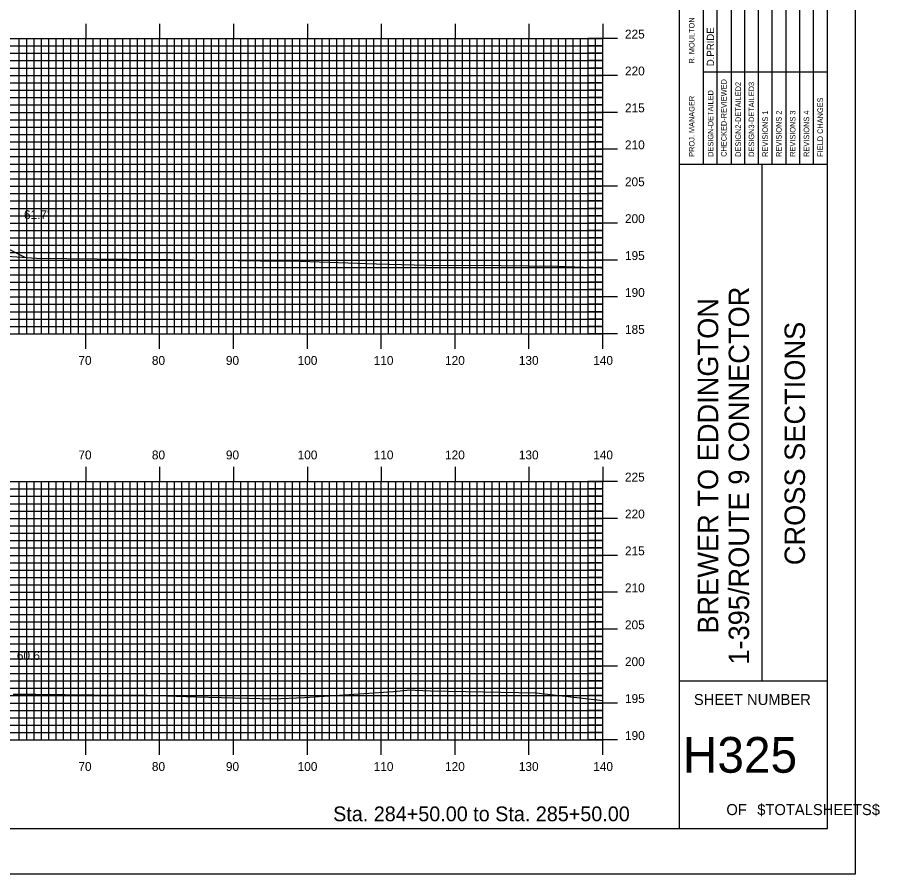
# Model space of a CAD drawing. Extents: x 1812161 to 1812504, y 442591 to 442811.
# Drawn here: x 1812387.2 to 1812503.9, y 442590.5 to 442706.6 of the extents above; entities that cross this region are included whole.
import ezdxf

# ---------------------------------------------------------------- set-up
doc = ezdxf.new("R2010")
doc.units = 0
for name, color, linetype in [('BORDER', 7, 'Continuous'), ('D_Roadway_Centerline', 7, 'Continuous'), ('D_Roadway_SlopeLines', 7, 'Continuous'), ('D_Text_Standard', 7, 'Continuous'), ('H_V ANNOTATION', 7, 'Continuous'), ('MAJOR', 7, 'Continuous'), ('MINOR', 7, 'Continuous'), ('PLOT BOUNDARY', 7, 'Continuous'), ('S_Roadway_Centerline', 7, 'Continuous')]:
    doc.layers.add(name, color=color, linetype=linetype)

msp = doc.modelspace()

# ---------------------------------------------------------------- linework, layer by layer
at = {"layer": 'BORDER'}
for p, q in [((1812476.83, 442596.67), (1812476.83, 442806.67)), ((1812476.83, 442686.67), (1812496.83, 442686.67)), ((1812488.01, 442616.67), (1812488.01, 442686.67)), ((1812476.83, 442616.67), (1812496.83, 442616.67))]:
    msp.add_line(p, q, dxfattribs=at)
msp.add_lwpolyline([(1812176.83, 442596.67), (1812496.83, 442596.67), (1812496.83, 442806.67), (1812176.83, 442806.67)], close=True, dxfattribs=at)
for points in [[(1812481.92, 442686.68), (1812481.92, 442721.67)], [(1812483.79, 442721.67), (1812483.79, 442686.68)], [(1812485.65, 442686.68), (1812485.65, 442721.67)], [(1812487.51, 442686.68), (1812487.51, 442721.67)], [(1812489.38, 442686.68), (1812489.38, 442721.67)], [(1812491.24, 442686.68), (1812491.24, 442721.67)], [(1812493.1, 442686.68), (1812493.1, 442721.67)], [(1812494.97, 442686.68), (1812494.97, 442721.67)], [(1812480.06, 442686.68), (1812480.06, 442720.26)], [(1812480.06, 442699.17), (1812496.83, 442699.17)]]:
    msp.add_lwpolyline(points, dxfattribs=at)
at = {"layer": 'D_Roadway_Centerline'}
msp.add_lwpolyline([(1812264.46, 442675.39), (1812298.22, 442692.27), (1812303.43, 442694.88), (1812306.43, 442694.94), (1812314.43, 442695.1), (1812326.43, 442694.52), (1812338.43, 442693.94), (1812346.43, 442693.56), (1812349.43, 442693.42), (1812354.96, 442690.65), (1812388.17, 442674.04)], dxfattribs=at)
at = {"layer": 'D_Roadway_SlopeLines'}
msp.add_lwpolyline([(1812349.43, 442693.42), (1812388.17, 442674.04)], dxfattribs=at)
at = {"layer": 'MAJOR'}
for p, q in [((1812396.43, 442705.67), (1812396.43, 442703.67)), ((1812406.43, 442705.67), (1812406.43, 442703.67)), ((1812416.43, 442705.67), (1812416.43, 442703.67)), ((1812426.43, 442705.67), (1812426.43, 442703.67)), ((1812436.43, 442705.67), (1812436.43, 442703.67)), ((1812446.43, 442705.67), (1812446.43, 442703.67)), ((1812456.43, 442705.67), (1812456.43, 442703.67)), ((1812466.43, 442705.67), (1812466.43, 442703.67)), ((1812186.43, 442703.67), (1812466.43, 442703.67)), ((1812186.43, 442703.67), (1812466.43, 442703.67)), ((1812396.43, 442663.67), (1812396.43, 442703.67)), ((1812406.43, 442663.67), (1812406.43, 442703.67)), ((1812416.43, 442663.67), (1812416.43, 442703.67)), ((1812426.43, 442663.67), (1812426.43, 442703.67)), ((1812436.43, 442663.67), (1812436.43, 442703.67)), ((1812446.43, 442663.67), (1812446.43, 442703.67)), ((1812456.43, 442663.67), (1812456.43, 442703.67)), ((1812468.43, 442703.67), (1812464.42, 442703.67)), ((1812466.43, 442663.67), (1812466.43, 442703.67)), ((1812466.43, 442663.67), (1812466.43, 442703.67)), ((1812186.43, 442698.67), (1812466.43, 442698.67)), ((1812468.43, 442698.67), (1812464.42, 442698.67)), ((1812186.43, 442693.67), (1812466.43, 442693.67)), ((1812468.43, 442693.67), (1812464.42, 442693.67)), ((1812186.43, 442688.67), (1812466.43, 442688.67)), ((1812468.43, 442688.67), (1812464.42, 442688.67)), ((1812186.43, 442683.67), (1812466.43, 442683.67)), ((1812468.43, 442683.67), (1812464.42, 442683.67)), ((1812186.43, 442678.67), (1812466.43, 442678.67)), ((1812468.43, 442678.67), (1812464.42, 442678.67)), ((1812186.43, 442673.67), (1812466.43, 442673.67)), ((1812468.43, 442673.67), (1812464.42, 442673.67)), ((1812186.43, 442668.67), (1812466.43, 442668.67)), ((1812468.43, 442668.67), (1812464.42, 442668.67)), ((1812186.43, 442663.67), (1812466.43, 442663.67)), ((1812186.43, 442663.67), (1812466.43, 442663.67)), ((1812396.43, 442661.66), (1812396.43, 442663.67)), ((1812406.43, 442661.66), (1812406.43, 442663.67)), ((1812416.43, 442661.66), (1812416.43, 442663.67)), ((1812426.43, 442661.66), (1812426.43, 442663.67)), ((1812436.43, 442661.66), (1812436.43, 442663.67)), ((1812446.43, 442661.66), (1812446.43, 442663.67)), ((1812456.43, 442661.66), (1812456.43, 442663.67)), ((1812468.43, 442663.67), (1812464.42, 442663.67)), ((1812466.43, 442661.66), (1812466.43, 442663.67)), ((1812396.43, 442645.67), (1812396.43, 442643.67)), ((1812406.43, 442645.67), (1812406.43, 442643.67)), ((1812416.43, 442645.67), (1812416.43, 442643.67)), ((1812426.43, 442645.67), (1812426.43, 442643.67)), ((1812436.43, 442645.67), (1812436.43, 442643.67)), ((1812446.43, 442645.67), (1812446.43, 442643.67)), ((1812456.43, 442645.67), (1812456.43, 442643.67)), ((1812466.43, 442645.67), (1812466.43, 442643.67)), ((1812186.43, 442643.67), (1812466.43, 442643.67)), ((1812186.43, 442643.67), (1812466.43, 442643.67)), ((1812396.43, 442608.67), (1812396.43, 442643.67)), ((1812406.43, 442608.67), (1812406.43, 442643.67)), ((1812416.43, 442608.67), (1812416.43, 442643.67)), ((1812426.43, 442608.67), (1812426.43, 442643.67)), ((1812436.43, 442608.67), (1812436.43, 442643.67)), ((1812446.43, 442608.67), (1812446.43, 442643.67)), ((1812456.43, 442608.67), (1812456.43, 442643.67)), ((1812468.43, 442643.67), (1812464.42, 442643.67)), ((1812466.43, 442608.67), (1812466.43, 442643.67)), ((1812466.43, 442608.67), (1812466.43, 442643.67)), ((1812186.43, 442638.67), (1812466.43, 442638.67)), ((1812468.43, 442638.67), (1812464.42, 442638.67)), ((1812186.43, 442633.67), (1812466.43, 442633.67)), ((1812468.43, 442633.67), (1812464.42, 442633.67)), ((1812186.43, 442628.67), (1812466.43, 442628.67)), ((1812468.43, 442628.67), (1812464.42, 442628.67)), ((1812186.43, 442623.67), (1812466.43, 442623.67)), ((1812468.43, 442623.67), (1812464.42, 442623.67)), ((1812186.43, 442618.67), (1812466.43, 442618.67)), ((1812468.43, 442618.67), (1812464.42, 442618.67)), ((1812186.43, 442613.67), (1812466.43, 442613.67)), ((1812468.43, 442613.67), (1812464.42, 442613.67)), ((1812186.43, 442608.67), (1812466.43, 442608.67)), ((1812186.43, 442608.67), (1812466.43, 442608.67)), ((1812396.43, 442606.66), (1812396.43, 442608.67)), ((1812406.43, 442606.66), (1812406.43, 442608.67)), ((1812416.43, 442606.66), (1812416.43, 442608.67)), ((1812426.43, 442606.66), (1812426.43, 442608.67)), ((1812436.43, 442606.66), (1812436.43, 442608.67)), ((1812446.43, 442606.66), (1812446.43, 442608.67)), ((1812456.43, 442606.66), (1812456.43, 442608.67)), ((1812468.43, 442608.67), (1812464.42, 442608.67)), ((1812466.43, 442606.66), (1812466.43, 442608.67))]:
    msp.add_line(p, q, dxfattribs=at)
at = {"layer": 'MINOR'}
for p, q in [((1812387.43, 442663.67), (1812387.43, 442703.67)), ((1812388.43, 442663.67), (1812388.43, 442703.67)), ((1812389.43, 442663.67), (1812389.43, 442703.67)), ((1812390.43, 442663.67), (1812390.43, 442703.67)), ((1812391.43, 442663.67), (1812391.43, 442703.67)), ((1812392.43, 442663.67), (1812392.43, 442703.67)), ((1812393.43, 442663.67), (1812393.43, 442703.67)), ((1812394.43, 442663.67), (1812394.43, 442703.67)), ((1812395.43, 442663.67), (1812395.43, 442703.67)), ((1812397.43, 442663.67), (1812397.43, 442703.67)), ((1812398.43, 442663.67), (1812398.43, 442703.67)), ((1812399.43, 442663.67), (1812399.43, 442703.67)), ((1812400.43, 442663.67), (1812400.43, 442703.67)), ((1812401.43, 442663.67), (1812401.43, 442703.67)), ((1812402.43, 442663.67), (1812402.43, 442703.67)), ((1812403.43, 442663.67), (1812403.43, 442703.67)), ((1812404.43, 442663.67), (1812404.43, 442703.67)), ((1812405.43, 442663.67), (1812405.43, 442703.67)), ((1812407.43, 442663.67), (1812407.43, 442703.67)), ((1812408.43, 442663.67), (1812408.43, 442703.67)), ((1812409.43, 442663.67), (1812409.43, 442703.67)), ((1812410.43, 442663.67), (1812410.43, 442703.67)), ((1812411.43, 442663.67), (1812411.43, 442703.67)), ((1812412.43, 442663.67), (1812412.43, 442703.67)), ((1812413.43, 442663.67), (1812413.43, 442703.67)), ((1812414.43, 442663.67), (1812414.43, 442703.67)), ((1812415.43, 442663.67), (1812415.43, 442703.67)), ((1812417.43, 442663.67), (1812417.43, 442703.67)), ((1812418.43, 442663.67), (1812418.43, 442703.67)), ((1812419.43, 442663.67), (1812419.43, 442703.67)), ((1812420.43, 442663.67), (1812420.43, 442703.67)), ((1812421.43, 442663.67), (1812421.43, 442703.67)), ((1812422.43, 442663.67), (1812422.43, 442703.67)), ((1812423.43, 442663.67), (1812423.43, 442703.67)), ((1812424.43, 442663.67), (1812424.43, 442703.67)), ((1812425.43, 442663.67), (1812425.43, 442703.67)), ((1812427.43, 442663.67), (1812427.43, 442703.67)), ((1812428.43, 442663.67), (1812428.43, 442703.67)), ((1812429.43, 442663.67), (1812429.43, 442703.67)), ((1812430.43, 442663.67), (1812430.43, 442703.67)), ((1812431.43, 442663.67), (1812431.43, 442703.67)), ((1812432.43, 442663.67), (1812432.43, 442703.67)), ((1812433.43, 442663.67), (1812433.43, 442703.67)), ((1812434.43, 442663.67), (1812434.43, 442703.67)), ((1812435.43, 442663.67), (1812435.43, 442703.67)), ((1812437.43, 442663.67), (1812437.43, 442703.67)), ((1812438.43, 442663.67), (1812438.43, 442703.67)), ((1812439.43, 442663.67), (1812439.43, 442703.67)), ((1812440.43, 442663.67), (1812440.43, 442703.67)), ((1812441.43, 442663.67), (1812441.43, 442703.67)), ((1812442.43, 442663.67), (1812442.43, 442703.67)), ((1812443.43, 442663.67), (1812443.43, 442703.67)), ((1812444.43, 442663.67), (1812444.43, 442703.67)), ((1812445.43, 442663.67), (1812445.43, 442703.67)), ((1812447.43, 442663.67), (1812447.43, 442703.67)), ((1812448.43, 442663.67), (1812448.43, 442703.67)), ((1812449.43, 442663.67), (1812449.43, 442703.67)), ((1812450.43, 442663.67), (1812450.43, 442703.67)), ((1812451.43, 442663.67), (1812451.43, 442703.67)), ((1812452.43, 442663.67), (1812452.43, 442703.67)), ((1812453.43, 442663.67), (1812453.43, 442703.67)), ((1812454.43, 442663.67), (1812454.43, 442703.67)), ((1812455.43, 442663.67), (1812455.43, 442703.67)), ((1812457.43, 442663.67), (1812457.43, 442703.67)), ((1812458.43, 442663.67), (1812458.43, 442703.67)), ((1812459.43, 442663.67), (1812459.43, 442703.67)), ((1812460.43, 442663.67), (1812460.43, 442703.67)), ((1812461.43, 442663.67), (1812461.43, 442703.67)), ((1812462.43, 442663.67), (1812462.43, 442703.67)), ((1812463.43, 442663.67), (1812463.43, 442703.67)), ((1812464.43, 442663.67), (1812464.43, 442703.67)), ((1812465.43, 442663.67), (1812465.43, 442703.67)), ((1812186.43, 442702.67), (1812466.43, 442702.67)), ((1812186.43, 442701.67), (1812466.43, 442701.67)), ((1812466.43, 442702.67), (1812464.42, 442702.67)), ((1812466.43, 442701.67), (1812464.42, 442701.67)), ((1812186.43, 442700.67), (1812466.43, 442700.67)), ((1812466.43, 442700.67), (1812464.42, 442700.67)), ((1812186.43, 442699.67), (1812466.43, 442699.67)), ((1812466.43, 442699.67), (1812464.42, 442699.67)), ((1812186.43, 442697.67), (1812466.43, 442697.67)), ((1812466.43, 442697.67), (1812464.42, 442697.67)), ((1812186.43, 442696.67), (1812466.43, 442696.67)), ((1812466.43, 442696.67), (1812464.42, 442696.67)), ((1812186.43, 442695.67), (1812466.43, 442695.67)), ((1812186.43, 442694.67), (1812466.43, 442694.67)), ((1812466.43, 442695.67), (1812464.42, 442695.67)), ((1812466.43, 442694.67), (1812464.42, 442694.67)), ((1812186.43, 442692.67), (1812466.43, 442692.67)), ((1812466.43, 442692.67), (1812464.42, 442692.67)), ((1812186.43, 442691.67), (1812466.43, 442691.67)), ((1812466.43, 442691.67), (1812464.42, 442691.67)), ((1812186.43, 442690.67), (1812466.43, 442690.67)), ((1812466.43, 442690.67), (1812464.42, 442690.67)), ((1812186.43, 442689.67), (1812466.43, 442689.67)), ((1812466.43, 442689.67), (1812464.42, 442689.67)), ((1812186.43, 442687.67), (1812466.43, 442687.67)), ((1812466.43, 442687.67), (1812464.42, 442687.67)), ((1812186.43, 442686.67), (1812466.43, 442686.67)), ((1812466.43, 442686.67), (1812464.42, 442686.67)), ((1812186.43, 442685.67), (1812466.43, 442685.67)), ((1812466.43, 442685.67), (1812464.42, 442685.67)), ((1812186.43, 442684.67), (1812466.43, 442684.67)), ((1812466.43, 442684.67), (1812464.42, 442684.67)), ((1812186.43, 442682.67), (1812466.43, 442682.67)), ((1812186.43, 442681.67), (1812466.43, 442681.67)), ((1812466.43, 442682.67), (1812464.42, 442682.67)), ((1812466.43, 442681.67), (1812464.42, 442681.67)), ((1812186.43, 442680.67), (1812466.43, 442680.67)), ((1812466.43, 442680.67), (1812464.42, 442680.67)), ((1812186.43, 442679.67), (1812466.43, 442679.67)), ((1812466.43, 442679.67), (1812464.42, 442679.67)), ((1812186.43, 442677.67), (1812466.43, 442677.67)), ((1812466.43, 442677.67), (1812464.42, 442677.67)), ((1812186.43, 442676.67), (1812466.43, 442676.67)), ((1812466.43, 442676.67), (1812464.42, 442676.67)), ((1812186.43, 442675.67), (1812466.43, 442675.67)), ((1812186.43, 442674.67), (1812466.43, 442674.67)), ((1812466.43, 442675.67), (1812464.42, 442675.67)), ((1812466.43, 442674.67), (1812464.42, 442674.67)), ((1812186.43, 442672.67), (1812466.43, 442672.67)), ((1812466.43, 442672.67), (1812464.42, 442672.67)), ((1812186.43, 442671.67), (1812466.43, 442671.67)), ((1812466.43, 442671.67), (1812464.42, 442671.67)), ((1812186.43, 442670.67), (1812466.43, 442670.67)), ((1812466.43, 442670.67), (1812464.42, 442670.67)), ((1812186.43, 442669.67), (1812466.43, 442669.67)), ((1812466.43, 442669.67), (1812464.42, 442669.67)), ((1812186.43, 442667.67), (1812466.43, 442667.67)), ((1812466.43, 442667.67), (1812464.42, 442667.67)), ((1812186.43, 442666.67), (1812466.43, 442666.67)), ((1812466.43, 442666.67), (1812464.42, 442666.67)), ((1812186.43, 442665.67), (1812466.43, 442665.67)), ((1812466.43, 442665.67), (1812464.42, 442665.67)), ((1812186.43, 442664.67), (1812466.43, 442664.67)), ((1812466.43, 442664.67), (1812464.42, 442664.67)), ((1812387.43, 442608.67), (1812387.43, 442643.67)), ((1812388.43, 442608.67), (1812388.43, 442643.67)), ((1812389.43, 442608.67), (1812389.43, 442643.67)), ((1812390.43, 442608.67), (1812390.43, 442643.67)), ((1812391.43, 442608.67), (1812391.43, 442643.67)), ((1812392.43, 442608.67), (1812392.43, 442643.67)), ((1812393.43, 442608.67), (1812393.43, 442643.67)), ((1812394.43, 442608.67), (1812394.43, 442643.67)), ((1812395.43, 442608.67), (1812395.43, 442643.67)), ((1812397.43, 442608.67), (1812397.43, 442643.67)), ((1812398.43, 442608.67), (1812398.43, 442643.67)), ((1812399.43, 442608.67), (1812399.43, 442643.67)), ((1812400.43, 442608.67), (1812400.43, 442643.67)), ((1812401.43, 442608.67), (1812401.43, 442643.67)), ((1812402.43, 442608.67), (1812402.43, 442643.67)), ((1812403.43, 442608.67), (1812403.43, 442643.67)), ((1812404.43, 442608.67), (1812404.43, 442643.67)), ((1812405.43, 442608.67), (1812405.43, 442643.67)), ((1812407.43, 442608.67), (1812407.43, 442643.67)), ((1812408.43, 442608.67), (1812408.43, 442643.67)), ((1812409.43, 442608.67), (1812409.43, 442643.67)), ((1812410.43, 442608.67), (1812410.43, 442643.67)), ((1812411.43, 442608.67), (1812411.43, 442643.67)), ((1812412.43, 442608.67), (1812412.43, 442643.67)), ((1812413.43, 442608.67), (1812413.43, 442643.67)), ((1812414.43, 442608.67), (1812414.43, 442643.67)), ((1812415.43, 442608.67), (1812415.43, 442643.67)), ((1812417.43, 442608.67), (1812417.43, 442643.67)), ((1812418.43, 442608.67), (1812418.43, 442643.67)), ((1812419.43, 442608.67), (1812419.43, 442643.67)), ((1812420.43, 442608.67), (1812420.43, 442643.67)), ((1812421.43, 442608.67), (1812421.43, 442643.67)), ((1812422.43, 442608.67), (1812422.43, 442643.67)), ((1812423.43, 442608.67), (1812423.43, 442643.67)), ((1812424.43, 442608.67), (1812424.43, 442643.67)), ((1812425.43, 442608.67), (1812425.43, 442643.67)), ((1812427.43, 442608.67), (1812427.43, 442643.67)), ((1812428.43, 442608.67), (1812428.43, 442643.67)), ((1812429.43, 442608.67), (1812429.43, 442643.67)), ((1812430.43, 442608.67), (1812430.43, 442643.67)), ((1812431.43, 442608.67), (1812431.43, 442643.67)), ((1812432.43, 442608.67), (1812432.43, 442643.67)), ((1812433.43, 442608.67), (1812433.43, 442643.67)), ((1812434.43, 442608.67), (1812434.43, 442643.67)), ((1812435.43, 442608.67), (1812435.43, 442643.67)), ((1812437.43, 442608.67), (1812437.43, 442643.67)), ((1812438.43, 442608.67), (1812438.43, 442643.67)), ((1812439.43, 442608.67), (1812439.43, 442643.67)), ((1812440.43, 442608.67), (1812440.43, 442643.67)), ((1812441.43, 442608.67), (1812441.43, 442643.67)), ((1812442.43, 442608.67), (1812442.43, 442643.67)), ((1812443.43, 442608.67), (1812443.43, 442643.67)), ((1812444.43, 442608.67), (1812444.43, 442643.67)), ((1812445.43, 442608.67), (1812445.43, 442643.67)), ((1812447.43, 442608.67), (1812447.43, 442643.67)), ((1812448.43, 442608.67), (1812448.43, 442643.67)), ((1812449.43, 442608.67), (1812449.43, 442643.67)), ((1812450.43, 442608.67), (1812450.43, 442643.67)), ((1812451.43, 442608.67), (1812451.43, 442643.67)), ((1812452.43, 442608.67), (1812452.43, 442643.67)), ((1812453.43, 442608.67), (1812453.43, 442643.67)), ((1812454.43, 442608.67), (1812454.43, 442643.67)), ((1812455.43, 442608.67), (1812455.43, 442643.67)), ((1812457.43, 442608.67), (1812457.43, 442643.67)), ((1812458.43, 442608.67), (1812458.43, 442643.67)), ((1812459.43, 442608.67), (1812459.43, 442643.67)), ((1812460.43, 442608.67), (1812460.43, 442643.67)), ((1812461.43, 442608.67), (1812461.43, 442643.67)), ((1812462.43, 442608.67), (1812462.43, 442643.67)), ((1812463.43, 442608.67), (1812463.43, 442643.67)), ((1812464.43, 442608.67), (1812464.43, 442643.67)), ((1812465.43, 442608.67), (1812465.43, 442643.67)), ((1812186.43, 442642.67), (1812466.43, 442642.67)), ((1812466.43, 442642.67), (1812464.42, 442642.67)), ((1812186.43, 442641.67), (1812466.43, 442641.67)), ((1812466.43, 442641.67), (1812464.42, 442641.67)), ((1812186.43, 442640.67), (1812466.43, 442640.67)), ((1812186.43, 442639.67), (1812466.43, 442639.67)), ((1812466.43, 442640.67), (1812464.42, 442640.67)), ((1812466.43, 442639.67), (1812464.42, 442639.67)), ((1812186.43, 442637.67), (1812466.43, 442637.67)), ((1812466.43, 442637.67), (1812464.42, 442637.67)), ((1812186.43, 442636.67), (1812466.43, 442636.67)), ((1812466.43, 442636.67), (1812464.42, 442636.67)), ((1812186.43, 442635.67), (1812466.43, 442635.67)), ((1812466.43, 442635.67), (1812464.42, 442635.67)), ((1812186.43, 442634.67), (1812466.43, 442634.67)), ((1812466.43, 442634.67), (1812464.42, 442634.67)), ((1812186.43, 442632.67), (1812466.43, 442632.67)), ((1812466.43, 442632.67), (1812464.42, 442632.67)), ((1812186.43, 442631.67), (1812466.43, 442631.67)), ((1812466.43, 442631.67), (1812464.42, 442631.67)), ((1812186.43, 442630.67), (1812466.43, 442630.67)), ((1812466.43, 442630.67), (1812464.42, 442630.67)), ((1812186.43, 442629.67), (1812466.43, 442629.67)), ((1812466.43, 442629.67), (1812464.42, 442629.67)), ((1812186.43, 442627.67), (1812466.43, 442627.67)), ((1812466.43, 442627.67), (1812464.42, 442627.67)), ((1812186.43, 442626.67), (1812466.43, 442626.67)), ((1812186.43, 442625.67), (1812466.43, 442625.67)), ((1812466.43, 442626.67), (1812464.42, 442626.67)), ((1812466.43, 442625.67), (1812464.42, 442625.67)), ((1812186.43, 442624.67), (1812466.43, 442624.67)), ((1812466.43, 442624.67), (1812464.42, 442624.67)), ((1812186.43, 442622.67), (1812466.43, 442622.67)), ((1812466.43, 442622.67), (1812464.42, 442622.67)), ((1812186.43, 442621.67), (1812466.43, 442621.67)), ((1812466.43, 442621.67), (1812464.42, 442621.67)), ((1812186.43, 442620.67), (1812466.43, 442620.67)), ((1812466.43, 442620.67), (1812464.42, 442620.67)), ((1812186.43, 442619.67), (1812466.43, 442619.67)), ((1812466.43, 442619.67), (1812464.42, 442619.67)), ((1812186.43, 442617.67), (1812466.43, 442617.67)), ((1812466.43, 442617.67), (1812464.42, 442617.67)), ((1812186.43, 442616.67), (1812466.43, 442616.67)), ((1812466.43, 442616.67), (1812464.42, 442616.67)), ((1812186.43, 442615.67), (1812466.43, 442615.67)), ((1812466.43, 442615.67), (1812464.42, 442615.67)), ((1812186.43, 442614.67), (1812466.43, 442614.67)), ((1812466.43, 442614.67), (1812464.42, 442614.67)), ((1812186.43, 442612.67), (1812466.43, 442612.67)), ((1812186.43, 442611.67), (1812466.43, 442611.67)), ((1812466.43, 442612.67), (1812464.42, 442612.67)), ((1812466.43, 442611.67), (1812464.42, 442611.67)), ((1812186.43, 442610.67), (1812466.43, 442610.67)), ((1812466.43, 442610.67), (1812464.42, 442610.67)), ((1812186.43, 442609.67), (1812466.43, 442609.67)), ((1812466.43, 442609.67), (1812464.42, 442609.67))]:
    msp.add_line(p, q, dxfattribs=at)
at = {"layer": 'PLOT BOUNDARY'}
msp.add_lwpolyline([(1812160.64, 442590.55), (1812500.64, 442590.55), (1812500.64, 442810.55), (1812160.64, 442810.55)], close=True, dxfattribs=at)
at = {"layer": 'S_Roadway_Centerline'}
for points in [[(1812382.38, 442674.43), (1812389.75, 442673.94), (1812406.13, 442673.75), (1812407.98, 442673.74), (1812420.04, 442673.57), (1812425.45, 442673.53), (1812435.8, 442673.14), (1812442.62, 442672.96), (1812452.64, 442672.93), (1812460.31, 442672.85), (1812466.16, 442672.62), (1812466.43, 442672.61)], [(1812386.61, 442614.87), (1812389.66, 442614.89), (1812397.53, 442614.8), (1812403.33, 442614.75), (1812404.74, 442614.72), (1812411.31, 442614.52), (1812421.74, 442614.22), (1812426.05, 442614.4), (1812438.08, 442615.25), (1812440.35, 442615.44), (1812441.01, 442615.41), (1812443.08, 442615.31), (1812457.43, 442615.04), (1812466.43, 442614.02)]]:
    msp.add_lwpolyline(points, dxfattribs=at)

# ---------------------------------------------------------------- texts
at = {"layer": 'BORDER'}
for s, height, p in [('R. MOULTON', 0.745, (1812478.84, 442700.28)), ('D.PRIDE', 0.969, (1812481.48, 442699.92)), ('CHECKED-REVIEWED', 0.7455, (1812483.19, 442687.65)), ('DESIGN2-DETAILED2', 0.7455, (1812485.13, 442687.65)), ('DESIGN3-DETAILED3', 0.7455, (1812486.92, 442687.65)), ('PROJ. MANAGER', 0.7455, (1812478.84, 442687.65)), ('DESIGN-DETAILED', 0.7455, (1812481.4, 442687.65)), ('FIELD CHANGES', 0.7455, (1812496.23, 442687.65)), ('REVISIONS 1', 0.7455, (1812488.78, 442687.65)), ('REVISIONS 2', 0.7455, (1812490.64, 442687.65)), ('REVISIONS 3', 0.7455, (1812492.51, 442687.65)), ('REVISIONS 4', 0.7455, (1812494.37, 442687.65)), ('1-395/ROUTE 9 CONNECTOR', 2.7557, (1812486.23, 442618.87)), ('BREWER TO EDDINGTON', 2.7557, (1812482.05, 442623.07)), ('CROSS SECTIONS', 2.7557, (1812493.8, 442632.34))]:
    msp.add_text(s, height=height, rotation=90, dxfattribs=at).set_placement(p)
for s, height, p in [('SHEET NUMBER', 1.4905, (1812478.76, 442613.4)), ('H325', 4.839, (1812477.27, 442604.23)), ('OF', 1.491, (1812483.16, 442598.49)), ('$TOTALSHEETS$', 1.4905, (1812487.34, 442598.49))]:
    msp.add_text(s, height=height, dxfattribs=at).set_placement(p)
at = {"layer": 'D_Text_Standard'}
for s, p in [("61.7'", (1812388.06, 442679.21)), ("60.6'", (1812387.1, 442619.5))]:
    msp.add_text(s, height=1.2, dxfattribs=at).set_placement(p)
at = {"layer": 'H_V ANNOTATION'}
for s, height, p in [('225', 1.2, (1812469.43, 442703.67)), ('220', 1.2, (1812469.43, 442698.67)), ('215', 1.2, (1812469.43, 442693.67)), ('210', 1.2, (1812469.43, 442688.67)), ('205', 1.2, (1812469.43, 442683.67)), ('200', 1.2, (1812469.43, 442678.67)), ('195', 1.2, (1812469.43, 442673.67)), ('190', 1.2, (1812469.43, 442668.67)), ('185', 1.2, (1812469.43, 442663.67)), ('70', 1.2, (1812395.43, 442659.47)), ('80', 1.2, (1812405.38, 442659.47)), ('90', 1.2, (1812415.4, 442659.47)), ('100', 1.2, (1812425.11, 442659.47)), ('110', 1.2, (1812435.41, 442659.47)), ('120', 1.2, (1812445.07, 442659.47)), ('130', 1.2, (1812455.06, 442659.47)), ('140', 1.2, (1812465.13, 442659.47)), ('70', 1.2, (1812395.43, 442646.67)), ('80', 1.2, (1812405.38, 442646.67)), ('90', 1.2, (1812415.4, 442646.67)), ('100', 1.2, (1812425.11, 442646.67)), ('110', 1.2, (1812435.41, 442646.67)), ('120', 1.2, (1812445.07, 442646.67)), ('130', 1.2, (1812455.06, 442646.67)), ('140', 1.2, (1812465.13, 442646.67)), ('225', 1.2, (1812469.43, 442643.67)), ('220', 1.2, (1812469.43, 442638.67)), ('215', 1.2, (1812469.43, 442633.67)), ('210', 1.2, (1812469.43, 442628.67)), ('205', 1.2, (1812469.43, 442623.67)), ('200', 1.2, (1812469.43, 442618.67)), ('195', 1.2, (1812469.43, 442613.67)), ('190', 1.2, (1812469.43, 442608.67)), ('70', 1.2, (1812395.43, 442604.47)), ('80', 1.2, (1812405.38, 442604.47)), ('90', 1.2, (1812415.4, 442604.47)), ('100', 1.2, (1812425.11, 442604.47)), ('110', 1.2, (1812435.41, 442604.47)), ('120', 1.2, (1812445.07, 442604.47)), ('130', 1.2, (1812455.06, 442604.47)), ('140', 1.2, (1812465.13, 442604.47)), ('Sta. 284+50.00 to Sta. 285+50.00', 2.0004, (1812429.92, 442597.66))]:
    msp.add_text(s, height=height, dxfattribs=at).set_placement(p)

doc.saveas('drawing.dxf')
